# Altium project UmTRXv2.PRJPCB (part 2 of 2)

## Sheet EEpromConfig.SchDoc: BaseBand Front-End
size A3; Revision: 1; SheetNumber: 7
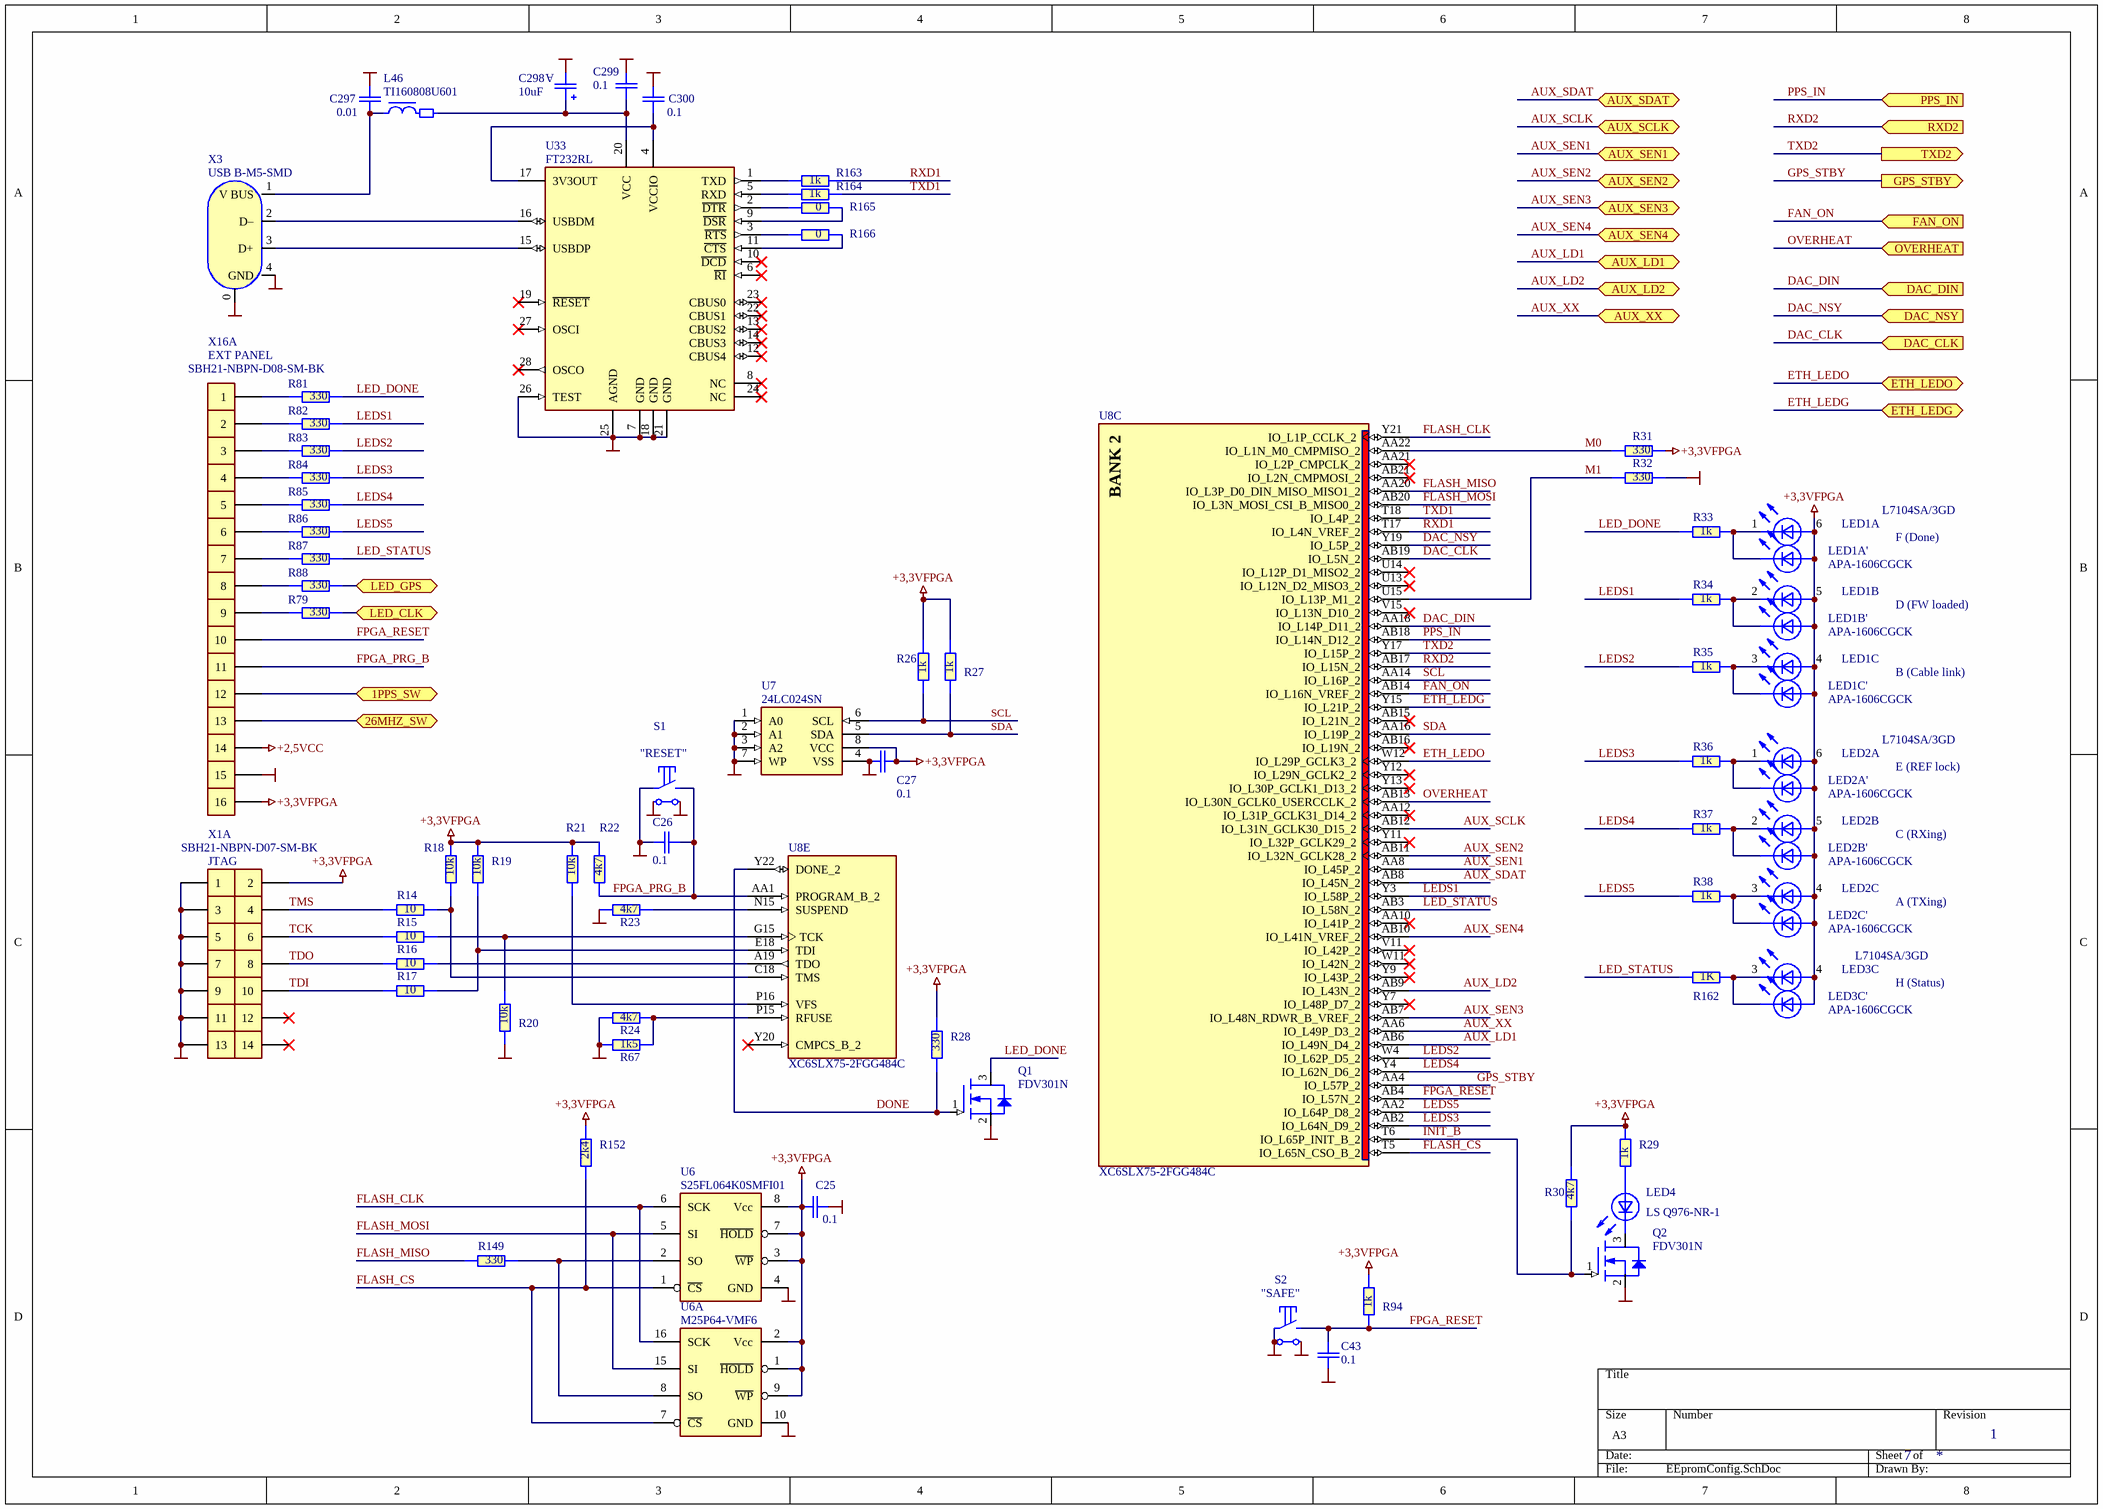
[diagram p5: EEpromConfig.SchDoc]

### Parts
C25  0.1  [C0402-Phillips]
C26  0.1  [C0402-Phillips]
C27  0.1  [C0402-Phillips]
C43  0.1  [C0402-Phillips]
C297  0.01  [C0603-PHILLIPS]
C298  10uF  [CA3216]
C299  0.1  [C0603-PHILLIPS]
C300  0.1  [C0603-PHILLIPS]
L46  TI160808U601  [Ti160808-Phillips]
LED1  L7104SA/3GD  [L-7104SA/3]  (value not drawn)  (parts A,B,C of 3)
LED1A'  APA-1606CGCK  [KPA-1606g]
LED1B'  APA-1606CGCK  [KPA-1606g]
LED1C'  APA-1606CGCK  [KPA-1606g]
LED2  L7104SA/3GD  [L-7104SA/3]  (value not drawn)  (parts A,B,C of 3)
LED2A'  APA-1606CGCK  [KPA-1606g]
LED2B'  APA-1606CGCK  [KPA-1606g]
LED2C'  APA-1606CGCK  [KPA-1606g]
LED3  L7104SA/3GD  [L-7104SA/3]  (part C of 3)
LED3C'  APA-1606CGCK  [KPA-1606g]
LED4  LS Q976-NR-1  [LED-0603y]
Q1  FDV301N  [SOT23-Philips]
Q2  FDV301N  [SOT23-Philips]
R14  10  [R0603-PHILLIPS]
R15  10  [R0603-PHILLIPS]
R16  10  [R0603-PHILLIPS]
R17  10  [R0603-PHILLIPS]
R18  10k  [R0603-PHILLIPS]
R19  10k  [R0603-PHILLIPS]
R20  10k  [R0603-PHILLIPS]
R21  10k  [R0603-PHILLIPS]
R22  4k7  [R0603-PHILLIPS]
R23  4k7  [R0603-PHILLIPS]
R24  4k7  [R0603-PHILLIPS]
R26  1k  [R0603-PHILLIPS]
R27  1k  [R0603-PHILLIPS]
R28  330  [R0603-PHILLIPS]
R29  1k  [R0603-PHILLIPS]
R30  4k7  [R0603-PHILLIPS]
R31  330  [R0603-PHILLIPS]
R32  330  [R0603-PHILLIPS]
R33  1k  [R0603-PHILLIPS]
R34  1k  [R0603-PHILLIPS]
R35  1k  [R0603-PHILLIPS]
R36  1k  [R0603-PHILLIPS]
R37  1k  [R0603-PHILLIPS]
R38  1k  [R0603-PHILLIPS]
R67  1k5  [R0603-PHILLIPS]
R79  330  [R0603-PHILLIPS]
R81  330  [R0603-PHILLIPS]
R82  330  [R0603-PHILLIPS]
R83  330  [R0603-PHILLIPS]
R84  330  [R0603-PHILLIPS]
R85  330  [R0603-PHILLIPS]
R86  330  [R0603-PHILLIPS]
R87  330  [R0603-PHILLIPS]
R88  330  [R0603-PHILLIPS]
R94  1k  [R0603-PHILLIPS]
R149  330  [R0603-PHILLIPS]
R152  2k4  [R0603-PHILLIPS]
R162  1K  [R0603-PHILLIPS]
R163  1k  [R0603-PHILLIPS]
R164  1k  [R0603-PHILLIPS]
R165  0  [R0603-PHILLIPS]
R166  0  [R0603-PHILLIPS]
S1  Misc: "RESET"  [TL3340]  (hidden comment: TL3340AF160QG)
S2  Misc: "SAFE"  [TL3340]  (hidden comment: TL3340AF160QG)
U6  S25FL064K0SMFI01  [SO-8[wide200]]
U6A  M25P64-VMF6  [so-16W]
U7  24LC024SN  [SOIC8]
U8  XC6SLX75-2FGG484C  [FBGA484]  (parts C,E of 8)
U33  FT232RL  [SSOP-28(5.3X10/0.65)]
X1  SBH21-NBPN-D07-SM-BK  Other: JTAG  [SBH-14]  (parts A,B,C,D,E,F,G,H,I,J,K,L,M,N of 14)
X3  USB B-M5-SMD  [USB/SM0.8-6H5]
X16  SBH21-NBPN-D08-SM-BK  Misc: EXT PANEL  [SBH-16]  (parts A,B,C,D,E,F,G,H,I,J,K,L,M,N,O,P of 16)

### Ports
1PPS_SW, 26MHZ_SW, AUX_LD1, AUX_LD2, AUX_SCLK, AUX_SDAT, AUX_SEN1, AUX_SEN2, AUX_SEN3, AUX_SEN4, AUX_XX, DAC_CLK (in), DAC_DIN (in), DAC_NSY (in), ETH_LEDG, ETH_LEDO, FAN_ON (in), GPS_STBY (out), LED_CLK, LED_GPS, OVERHEAT (in), PPS_IN (in), RXD2 (in), TXD2 (out)

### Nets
+2,5VCC: X16.14
+3,3VFPGA: C25.1 C27.2 LED1.4(A3) LED1.5(A2) LED1.6(A1) LED1A'.2(A) LED1B'.2(A) LED1C'.2(A) LED2.4(A3) LED2.5(A2) LED2.6(A1) LED2A'.2(A) LED2B'.2(A) LED2C'.2(A) LED3.4(A3) LED3C'.2(A) R18.1 R19.1 R21.1 R22.1 R26.1 R27.1 R28.1 R29.1 R30.1 R31.2 R94.1 R152.1 U6.3(~{WP}) U6.7(~{HOLD}) U6.8(Vcc) U6A.1(~{HOLD}) U6A.2(Vcc) U6A.9(~{WP}) U7.8(VCC) X1.2 X16.16
GND: C25.2 C26.2 C27.1 C43.1 C297.1 C298.2(-) C299.1 C300.1 Q1.2(S) Q2.2(S) R20.2 R23.1 R24.1 R32.2 R67.1 S1.2 S1.3 S1.4 S2.2 S2.3 S2.4 U6.4(GND) U6A.10(GND) U7.1(A0) U7.2(A1) U7.3(A2) U7.4(VSS) U7.7(WP) U33.7(GND) U33.18(GND) U33.21(GND) U33.25(AGND) U33.26(TEST) X1.1 X1.3 X1.5 X1.7 X1.9 X1.11 X1.13 X3.0(GND) X3.4(GND) X16.15
1PPS_SW: X16.12 ; port 1PPS_SW
26MHZ_SW: X16.13 ; port 26MHZ_SW
AUX_LD1: U8.AB6(IO_L49N_D4_2) ; port AUX_LD1
AUX_LD2: U8.AB9(IO_L43N_2) ; port AUX_LD2
AUX_SCLK: U8.AB12(IO_L31N_GCLK30_D15_2) ; port AUX_SCLK
AUX_SDAT: U8.AB8(IO_L45N_2) ; port AUX_SDAT
AUX_SEN1: U8.AA8(IO_L45P_2) ; port AUX_SEN1
AUX_SEN2: U8.AB11(IO_L32N_GCLK28_2) ; port AUX_SEN2
AUX_SEN3: U8.AB7(IO_L48N_RDWR_B_VREF_2) ; port AUX_SEN3
AUX_SEN4: U8.AB10(IO_L41N_VREF_2) ; port AUX_SEN4
AUX_XX: U8.AA6(IO_L49P_D3_2) ; port AUX_XX
DAC_CLK: U8.AB19(IO_L5N_2) ; port DAC_CLK
DAC_DIN: U8.AA18(IO_L14P_D11_2) ; port DAC_DIN
DAC_NSY: U8.Y19(IO_L5P_2) ; port DAC_NSY
DONE: Q1.1(G) R28.2 U8.Y22(DONE_2)
ETH_LEDG: U8.Y15(IO_L21P_2) ; port ETH_LEDG
ETH_LEDO: U8.W12(IO_L29P_GCLK3_2) ; port ETH_LEDO
FAN_ON: U8.AB14(IO_L16N_VREF_2) ; port FAN_ON
FLASH_CLK: U6.6(SCK) U6A.16(SCK) U8.Y21(IO_L1P_CCLK_2)
FLASH_CS: R152.2 U6.1(~{CS}) U6A.7(~{CS}) U8.T5(IO_L65N_CSO_B_2)
FLASH_MISO: R149.1 U8.AA20(IO_L3P_D0_DIN_MISO_MISO1_2)
FLASH_MOSI: U6.5(SI) U6A.15(SI) U8.AB20(IO_L3N_MOSI_CSI_B_MISO0_2)
FPGA_PRG_B: C26.1 R22.2 S1.1 U8.AA1(PROGRAM_B_2) X16.11
FPGA_RESET: C43.2 R94.2 S2.1 U8.AB4(IO_L57N_2) X16.10
GPS_STBY: U8.AA4(IO_L57P_2) ; port GPS_STBY
INIT_B: Q2.1(G) R30.2 U8.T6(IO_L65P_INIT_B_2)
LED_CLK: R79.2 ; port LED_CLK
LED_DONE: Q1.3(D) R33.2 R81.2
LED_GPS: R88.2 ; port LED_GPS
LED_STATUS: R87.2 R162.1 U8.AB3(IO_L58N_2)
LEDS1: R34.2 R82.2 U8.Y3(IO_L58P_2)
LEDS2: R35.2 R83.2 U8.W4(IO_L62P_D5_2)
LEDS3: R36.2 R84.2 U8.AB2(IO_L64N_D9_2)
LEDS4: R37.2 R85.2 U8.Y4(IO_L62N_D6_2)
LEDS5: R38.2 R86.2 U8.AA2(IO_L64P_D8_2)
M0: R31.1 U8.AA22(IO_L1N_M0_CMPMISO_2)
M1: R32.1 U8.U15(IO_L13P_M1_2)
OVERHEAT: U8.AB13(IO_L30N_GCLK0_USERCCLK_2) ; port OVERHEAT
PPS_IN: U8.AB18(IO_L14N_D12_2) ; port PPS_IN
RXD1: R163.1 U8.T17(IO_L4N_VREF_2)
RXD2: U8.AB17(IO_L15N_2) ; port RXD2
SCL: R26.2 U7.6(SCL) U8.AA14(IO_L16P_2)
SDA: R27.2 U7.5(SDA) U8.AA16(IO_L19P_2)
TCK: R15.1 X1.6
TDI: R17.1 X1.10
TDO: R16.1 X1.8
TMS: R14.1 X1.4
TXD1: R164.1 U8.T18(IO_L4P_2)
TXD2: U8.Y17(IO_L15P_2) ; port TXD2
NetC297_2: C297.2 L46.1 X3.1(V_BUS)
NetC298_1: C298.1(+) C299.2 L46.2 U33.20(VCC)
NetC300_2: C300.2 U33.4(VCCIO) U33.17(3V3OUT)
NetLED1_1: LED1.1(K1) LED1A'.1(K) R33.1
NetLED1_2: LED1.2(K2) LED1B'.1(K) R34.1
NetLED1_3: LED1.3(K3) LED1C'.1(K) R35.1
NetLED2_1: LED2.1(K1) LED2A'.1(K) R36.1
NetLED2_2: LED2.2(K2) LED2B'.1(K) R37.1
NetLED2_3: LED2.3(K3) LED2C'.1(K) R38.1
NetLED3_3: LED3.3(K3) LED3C'.1(K) R162.2
NetLED4_1: LED4.1(K) Q2.3(D)
NetLED4_2: LED4.2(A) R29.2
NetR14_2: R14.2 R18.2 U8.C18(TMS)
NetR15_2: R15.2 R20.1 U8.G15(TCK)
NetR16_2: R16.2 U8.A19(TDO)
NetR17_2: R17.2 R19.2 U8.E18(TDI)
NetR21_2: R21.2 U8.P16(VFS)
NetR23_2: R23.2 U8.N15(SUSPEND)
NetR24_2: R24.2 R67.2 U8.P15(RFUSE)
NetR79_1: R79.1 X16.9
NetR81_1: R81.1 X16.1
NetR82_1: R82.1 X16.2
NetR83_1: R83.1 X16.3
NetR84_1: R84.1 X16.4
NetR85_1: R85.1 X16.5
NetR86_1: R86.1 X16.6
NetR87_1: R87.1 X16.7
NetR88_1: R88.1 X16.8
NetR149_2: R149.2 U6.2(SO) U6A.8(SO)
NetR163_2: R163.2 U33.1(TXD)
NetR164_2: R164.2 U33.5(RXD)
NetR165_1: R165.1 U33.2(~{DTR})
NetR165_2: R165.2 U33.9(~{DSR})
NetR166_1: R166.1 U33.3(~{RTS})
NetR166_2: R166.2 U33.11(~{CTS})
NetU33_15: U33.15(USBDP) X3.3(D+)
NetU33_16: U33.16(USBDM) X3.2(D–)

Not connected (* = marked no-connect by the designer): U8 AA10(IO_L41P_2)* AA12(IO_L31P_GCLK31_D14_2)* AA21(IO_L2P_CMPCLK_2)* AB15(IO_L21N_2)* AB16(IO_L19N_2)* AB21(IO_L2N_CMPMOSI_2)* U13(IO_L12N_D2_MISO3_2)* U14(IO_L12P_D1_MISO2_2)* V11(IO_L42P_2)* V15(IO_L13N_D10_2)* W11(IO_L42N_2)* Y7(IO_L48P_D7_2)* Y9(IO_L43P_2)* Y11(IO_L32P_GCLK29_2)* Y12(IO_L29N_GCLK2_2)* Y13(IO_L30P_GCLK1_D13_2)* Y20(CMPCS_B_2)*; U33 6(~{RI})* 8(NC)* 10(~{DCD})* 12(CBUS4)* 13(CBUS2)* 14(CBUS3)* 19(~{RESET})* 22(CBUS1)* 23(CBUS0)* 24(NC)* 27(OSCI)* 28(OSCO)*; X1 12* 14*

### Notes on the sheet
- F (Done)
- D (FW loaded)
- B (Cable link)
- E (REF lock)
- C (RXing)
- A (TXing)
- H (Status)

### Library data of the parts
C25-C27 C43 = C0402: Конденсатор; Manufacturer: MURATA; Tolerance: 20%; Name: SMD0402; U/P/TKE: Y5V
C297 = C0603: Конденсатор; Manufacturer: MURATA; Tolerance: 20%; Name: SMD0603; U/P/TKE: X7R
C298 = CA3216: Конденсатор; Manufacturer: SPRAGUE; Name: Case A; U/P/TKE: 10V
C299 C300 = C0603: Конденсатор; Manufacturer: MURATA; Tolerance: 20%; Name: SMD0603; U/P/TKE: Y5V
L46 = TI160808: Дроссель ЭМС; Manufacturer: MURATA
LED1-LED3 = L7104SA/3: Светодиод; Manufacturer: KINGBRIGTH; PDF: d:\Proj\Components\Kingbright\L-7104SA-3GD(Ver.4).pdf
LED1A' LED1B' LED1C' LED2A' LED2B' LED2C' LED3C' = KPA-1606: Светодиод; Manufacturer: Kingbright
LED4 = LED0603: LED SMD; Manufacturer: OSRAM Opto Semiconductors Inc
Q1 Q2 = FDV301N: Транзистор; Manufacturer: Fairchild; PDF: D:\Proj\Components\FairChild\FDV301N.pdf
R14-R24 R26-R38 R67 R79 R81-R88 R94 R149 R152 R162-R166 = R0603: Резистор; Manufacturer: YAGEO; Tolerance: 5%; Name: SMD0603; U/P/TKE: 0.1W
S1 S2 = TL3340AF160QG: Switch Tactile SMD right angle; Manufacturer: E-Switch
U6 = S25FL064K: Микросхема; Manufacturer: SPANSION; Swap: No
U6A = M25P64-VMF6: Микросхема; Manufacturer: ST; Swap: No
U7 = AT24CXX: Микросхема; Manufacturer: Microchip; Swap: No; PDF: d:\Proj\components\Atmel\AT24C02A_04A_08A_16A.pdf; PDF2: d:\Proj\Components\Atmel\AT24C04B_08B.pdf
U8 = XC6SLX75-2FGG484C: Spartan-6 LX 1.2V FPGA, 270 User I/Os, 484-Ball Fine-Pitch BGA (1.0mm Pitch), Speed Grade 2, Commercial Grade, Pb-Free; Manufacturer: Xilinx
U33 = FT232RL: Микросхема; Manufacturer: FTDI; Misc: USB UART Asynchronous Serial Data Transfer Chip,
X1 = SBH21-7x2_SMD: Разъем; Manufacturer: Sullins
X3 = USB M-1J: Разъём
X16 = SBH21-8x2_SMD: Connector 2mm SMD; Manufacturer: Sullins

## Sheet Clocking.SchDoc: BaseBand Front-End
size A3; Revision: 1; SheetNumber: 5
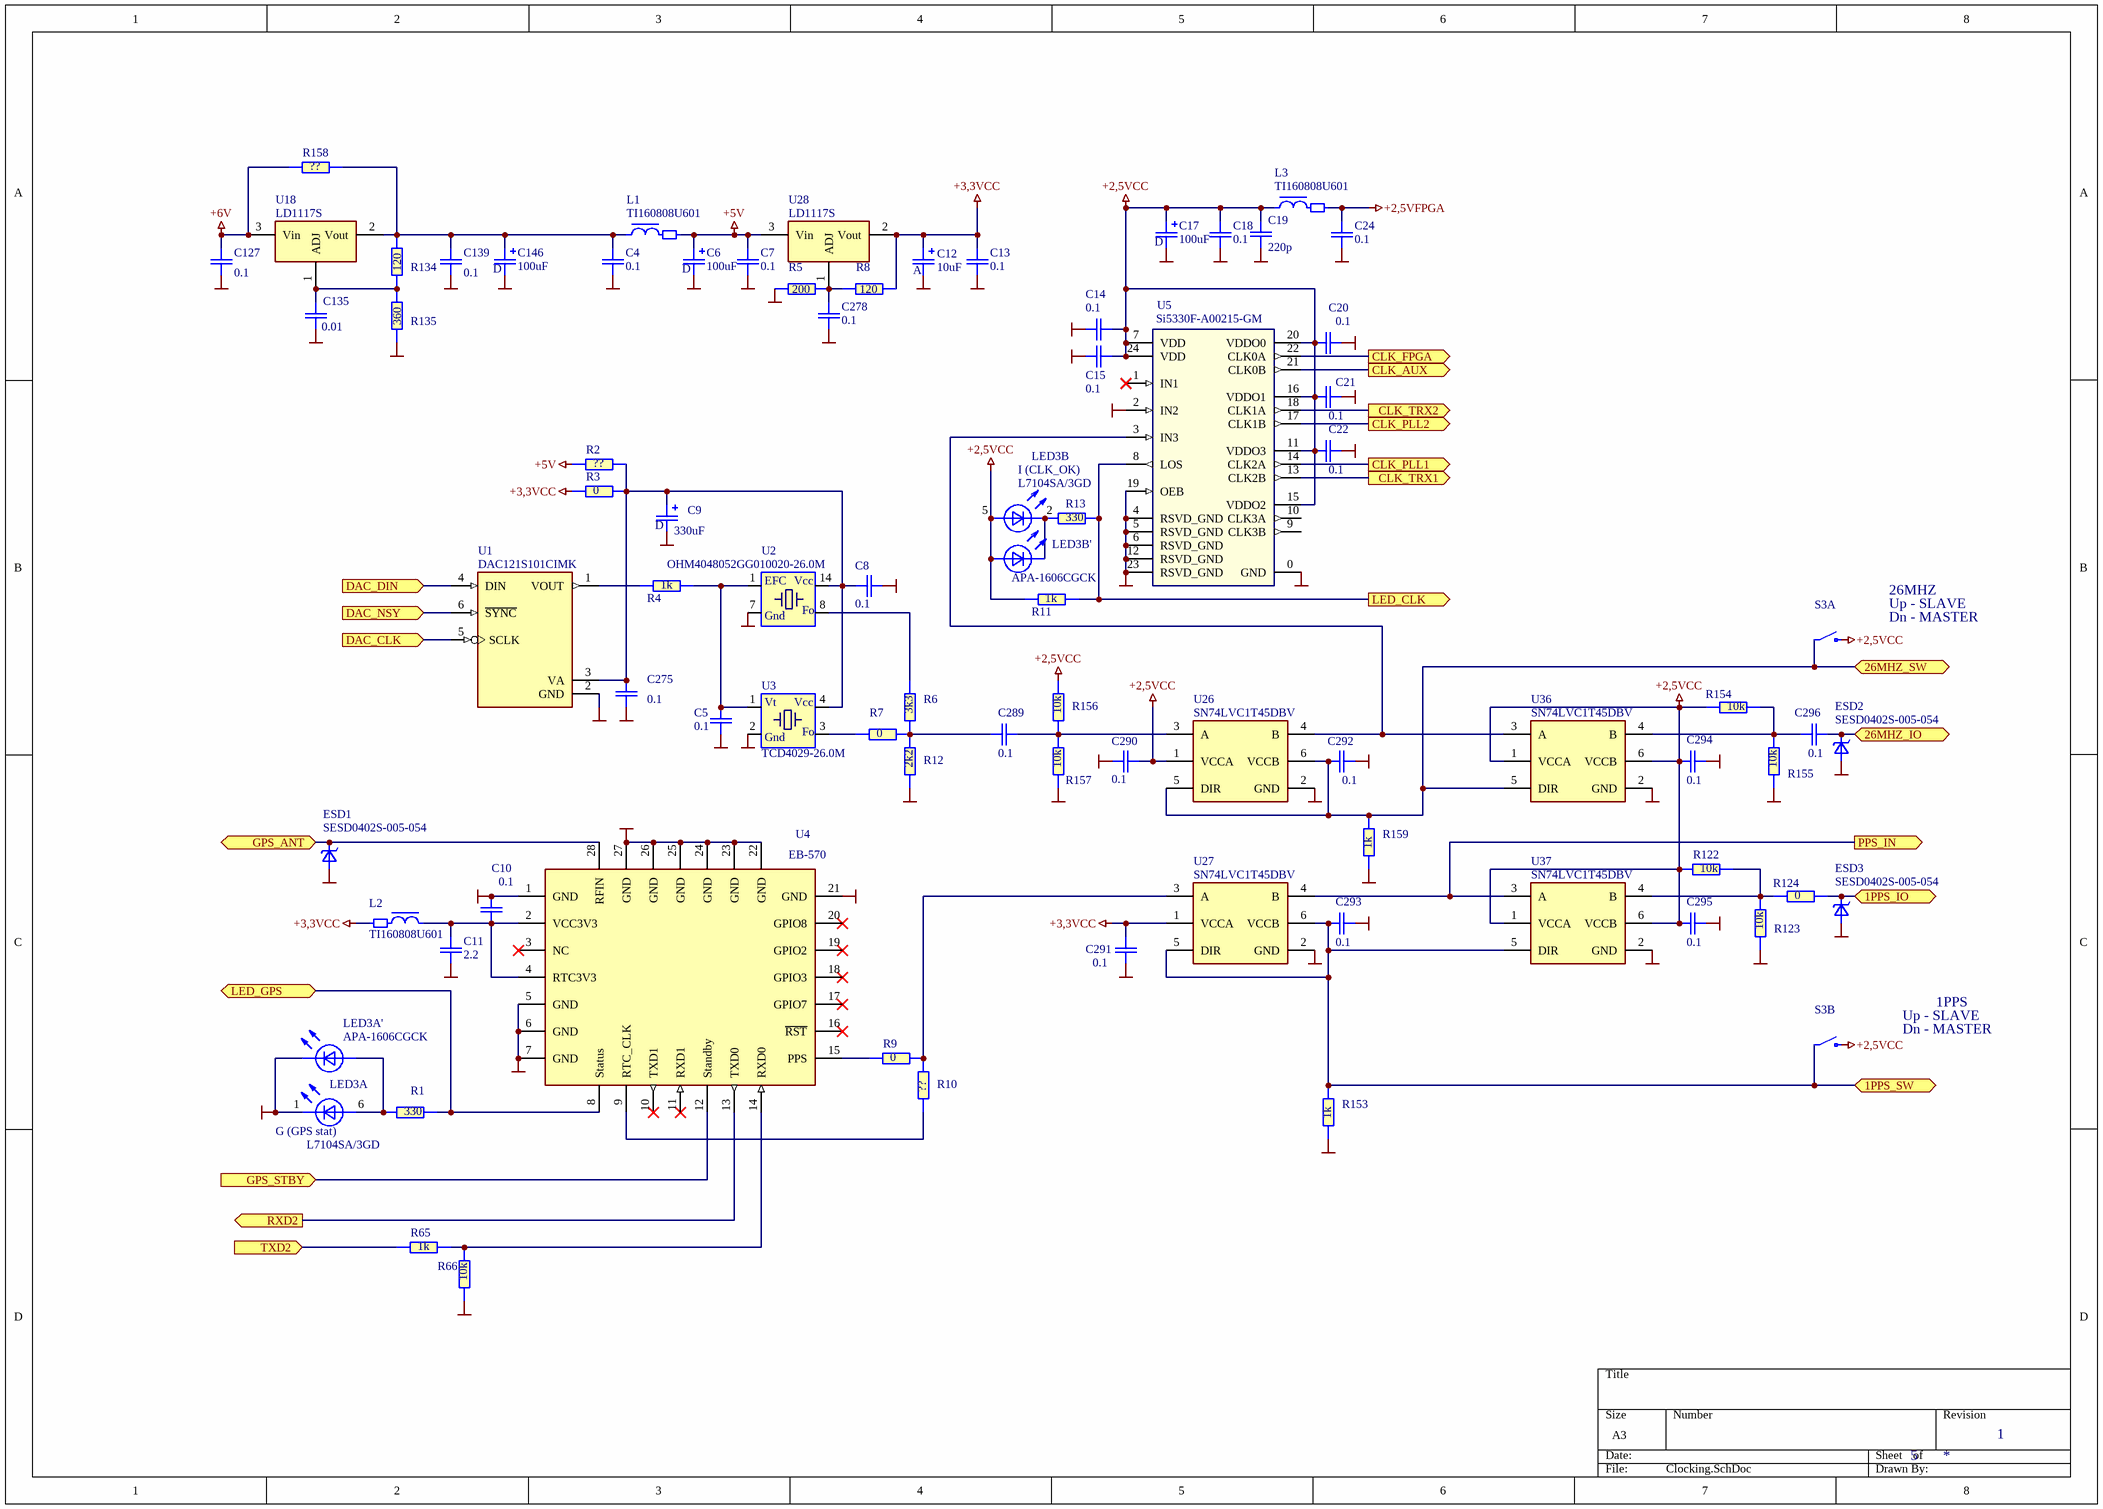
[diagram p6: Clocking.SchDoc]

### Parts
C4  0.1  [C0402-Phillips]
C5  0.1  [C0402-Phillips]
C6  100uF  [cd7343]
C7  0.1  [C0402-Phillips]
C8  0.1  [C0402-Phillips]
C9  330uF  [cd7343]
C10  0.1  [C0402-Phillips]
C11  2.2  [C0402-Phillips]
C12  10uF  [CA3216]
C13  0.1  [C0402-Phillips]
C14  0.1  [C0402-Phillips]
C15  0.1  [C0402-Phillips]
C17  100uF  [cd7343]
C18  0.1  [C0402-Phillips]
C19  220p  [C0603-PHILLIPS]
C20  0.1  [C0402-Phillips]
C21  0.1  [C0402-Phillips]
C22  0.1  [C0402-Phillips]
C24  0.1  [C0402-Phillips]
C127  0.1  [C0402-Phillips]
C135  0.01  [C0402-Phillips]
C139  0.1  [C0402-Phillips]
C146  100uF  [cd7343]
C275  0.1  [C0402-Phillips]
C278  0.1  [C0402-Phillips]
C289  0.1  [C0402-Phillips]
C290  0.1  [C0402-Phillips]
C291  0.1  [C0402-Phillips]
C292  0.1  [C0402-Phillips]
C293  0.1  [C0402-Phillips]
C294  0.1  [C0402-Phillips]
C295  0.1  [C0402-Phillips]
C296  0.1  [C0402-Phillips]
ESD1  SESD0402S-005-054  [SESD0402-Phillips]
ESD2  SESD0402S-005-054  [SESD0402-Phillips]
ESD3  SESD0402S-005-054  [SESD0402-Phillips]
L1  TI160808U601  [Ti160808-Phillips]
L2  TI160808U601  [Ti160808-Phillips]
L3  TI160808U601  [Ti160808-Phillips]
LED3  L7104SA/3GD  [L-7104SA/3]  (parts A,B of 3)
LED3A'  APA-1606CGCK  [KPA-1606g]
LED3B'  APA-1606CGCK  [KPA-1606g]
R1  330  [R0603-PHILLIPS]
R2  ??  [R0603-PHILLIPS]
R3  0  [R0603-PHILLIPS]
R4  1k  [R0603-PHILLIPS]
R5  200  [R0603-PHILLIPS]
R6  3k3  [R0603-PHILLIPS]
R7  0  [R0603-PHILLIPS]
R8  120  [R0603-PHILLIPS]
R9  0  [R0603-PHILLIPS]
R10  ??  [R0603-PHILLIPS]
R11  1k  [R0603-PHILLIPS]
R12  2k2  [R0603-PHILLIPS]
R13  330  [R0603-PHILLIPS]
R65  1k  [R0603-PHILLIPS]
R66  10k  [R0603-PHILLIPS]
R122  10k  [R0603-PHILLIPS]
R123  10k  [R0603-PHILLIPS]
R124  0  [R0603-PHILLIPS]
R134  120  [R0603-PHILLIPS]
R135  360  [R0603-PHILLIPS]
R153  1k  [R0603-PHILLIPS]
R154  10k  [R0603-PHILLIPS]
R155  10k  [R0603-PHILLIPS]
R156  10k  [R0603-PHILLIPS]
R157  10k  [R0603-PHILLIPS]
R158  ??  [R0603-PHILLIPS]
R159  1k  [R0603-PHILLIPS]
S3  CHP-021A  [CHP-02xA]  (value not drawn)  (parts A,B of 2)
U1  DAC121S101CIMK  [SOT-23-6]
U2  OHM4048052GG010020-26.0M  [DIL14-20x13,2]
U3  TCD4029-26.0M  [TCXO5X3]
U4  EB-570  [EB-570]
U5  Si5330F-A00215-GM  [QFN-24(4x4/0/5mm) with Pad]
U18  LD1117S  [SOT-223-1]
U26  SN74LVC1T45DBV  [SOT-23-6-min]
U27  SN74LVC1T45DBV  [SOT-23-6-min]
U28  LD1117S  [SOT-223-1]
U36  SN74LVC1T45DBV  [SOT-23-6-min]
U37  SN74LVC1T45DBV  [SOT-23-6-min]

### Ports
1PPS_IO, 1PPS_SW, 26MHZ_IO, 26MHZ_SW, CLK_AUX (out), CLK_FPGA (out), CLK_PLL1 (out), CLK_PLL2 (out), CLK_TRX1 (out), CLK_TRX2 (out), DAC_CLK (in), DAC_DIN (in), DAC_NSY (in), GPS_ANT, GPS_STBY (in), LED_CLK (out), LED_GPS, PPS_IN (out), RXD2 (out), TXD2 (in)

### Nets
+2,5VCC: C14.2 C15.2 C17.1(+) C18.1 C19.1 C20.1 C21.1 C22.1 C290.1 C294.2 C295.2 L3.1 LED3.5(A2) LED3B'.2(A) R11.1 R122.2 R154.2 R156.1 S3.3 S3.4 U5.7(VDD) U5.11(VDDO3) U5.15(VDDO2) U5.16(VDDO1) U5.20(VDDO0) U5.24(VDD) U26.1(VCCA) U36.1(VCCA) U36.6(VCCB) U37.1(VCCA) U37.6(VCCB)
+2,5VFPGA: C24.1 L3.2
+3,3VCC: C12.1(+) C13.1 C291.1 L2.2 R3.1 R8.2 U27.1(VCCA) U28.2(Vout)
+5V: C6.1(+) C7.1 L1.2 R2.1 U28.3(Vin)
+6V: C127.1 R158.1 U18.3(Vin)
GND: C4.2 C5.1 C6.2(-) C7.2 C8.2 C9.2(-) C10.2 C11.2 C12.2(-) C13.2 C14.1 C15.1 C17.2(-) C18.2 C19.2 C20.2 C21.2 C22.2 C24.2 C127.2 C135.2 C139.2 C146.2(-) C275.1 C278.2 C290.2 C291.2 C292.1 C293.1 C294.1 C295.1 ESD1.2(A) ESD2.2(A) ESD3.2(A) LED3.1(K1) LED3A'.1(K) R5.1 R12.1 R66.1 R123.2 R135.2 R153.1 R155.2 R157.2 R159.1 U1.2(GND) U2.7(GND) U3.2(GND) U4.1(GND) U4.5(GND) U4.6(GND) U4.7(GND) U4.21(GND) U4.22(GND) U4.23(GND) U4.24(GND) U4.25(GND) U4.26(GND) U4.27(GND) U5.0(GND) U5.2(IN2) U5.4(RSVD_GND) U5.5(RSVD_GND) U5.6(RSVD_GND) U5.12(RSVD_GND) U5.19(OEB) U5.23(RSVD_GND) U26.2(GND) U27.2(GND) U36.2(GND) U37.2(GND)
1PPS_IO: ESD3.1(K) R124.1 ; port 1PPS_IO
1PPS_SW: C293.2 R153.2 S3.2 U27.5(DIR) U27.6(VCCB) U37.5(DIR) ; port 1PPS_SW
26MHZ_IO: C296.1 ESD2.1(K) ; port 26MHZ_IO
26MHZ_SW: C292.2 R159.2 S3.1 U26.5(DIR) U26.6(VCCB) U36.5(DIR) ; port 26MHZ_SW
CLK_AUX: U5.21(CLK0B) ; port CLK_AUX
CLK_FPGA: U5.22(CLK0A) ; port CLK_FPGA
CLK_PLL1: U5.14(CLK2A) ; port CLK_PLL1
CLK_PLL2: U5.17(CLK1B) ; port CLK_PLL2
CLK_TRX1: U5.13(CLK2B) ; port CLK_TRX1
CLK_TRX2: U5.18(CLK1A) ; port CLK_TRX2
DAC_CLK: U1.5(SCLK) ; port DAC_CLK
DAC_DIN: U1.4(DIN) ; port DAC_DIN
DAC_NSY: U1.6(~{SYNC}) ; port DAC_NSY
GPS_ANT: ESD1.1(K) U4.28(RFIN) ; port GPS_ANT
GPS_STBY: U4.12(Standby) ; port GPS_STBY
LED_CLK: R11.2 R13.2 U5.8(LOS) ; port LED_CLK
LED_GPS: R1.2 U4.8(Status) ; port LED_GPS
PPS_IN: U27.4(B) U37.3(A) ; port PPS_IN
RXD2: U4.13(TXD0) ; port RXD2
TXD2: R65.1 ; port TXD2
NetC4_1: C4.1 C139.1 C146.1(+) L1.1 R134.1 R158.2 U18.2(Vout)
NetC5_2: C5.2 R4.2 U2.1(EFC) U3.1(Vtune)
NetC8_1: C8.1 C9.1(+) C275.2 R2.2 R3.2 U1.3(VA) U2.14(VCC) U3.4(VCC)
NetC10_1: C10.1 C11.1 L2.1 U4.2(VCC3V3) U4.4(RTC3V3)
NetC135_1: C135.1 R134.2 R135.1 U18.1(ADJ)
NetC278_1: C278.1 R5.2 R8.1 U28.1(ADJ)
NetC289_1: C289.1 R156.2 R157.1 U26.3(A)
NetC289_2: C289.2 R6.2 R7.2 R12.2
NetC296_2: C296.2 R154.1 R155.1 U36.4(B)
NetLED3_2: LED3.2(K2) LED3B'.1(K) R13.1
NetLED3_6: LED3.6(A1) LED3A'.2(A) R1.1
NetR4_1: R4.1 U1.1(VOUT)
NetR6_1: R6.1 U2.8(Fo)
NetR7_1: R7.1 U3.3(Fo)
NetR9_1: R9.1 U4.15(PPS)
NetR9_2: R9.2 R10.2 U27.3(A)
NetR10_1: R10.1 U4.9(RTC_CLK)
NetR65_2: R65.2 R66.2 U4.14(RXD0)
NetR122_1: R122.1 R123.1 R124.2 U37.4(B)
NetU5_3: U5.3(IN3) U26.4(B) U36.3(A)

Not connected (* = marked no-connect by the designer): U4 3(NC)* 10(TXD1)* 11(RXD1)* 16(~{RST})* 17(GPIO7)* 18(GPIO3)* 19(GPIO2)* 20(GPIO8)*; U5 1(IN1)* 9(CLK3B) 10(CLK3A)

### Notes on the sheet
- I (CLK_OK)
- (near S3) Dn - MASTER
- Up - SLAVE
- 26MHZ
- Dn - MASTER
- 1PPS
- (near LED3) G (GPS stat)

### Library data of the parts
C4 C5 C7 C8 C10 C11 C13-C15 C18 C20-C22 C24 C127 C135 C139 C275 C278 C289-C296 = C0402: as C25-C27 on sheet EEpromConfig
C6 C17 C146 = CD7343: Конденсатор; Manufacturer: SPRAGUE; Name: CASE-G; U/P/TKE: 16V
C9 = CD7343: Конденсатор; Manufacturer: Kemet; Name: CASE-D; U/P/TKE: 10V
C12 = CA3216: as C298 on sheet EEpromConfig
C19 = C0603: Конденсатор; Manufacturer: MURATA; Tolerance: 20%; Name: SMD0603; U/P/TKE: NP0
ESD1-ESD3 = SESD0402S: ESD diod unidirectional; Manufacturer: Tyco Electronics Corp; U/P/TKE: 5.4V
L1-L3 = TI160808: Дроссель ЭМС; Manufacturer: MURATA
LED3 = L7104SA/3: as LED1 on sheet EEpromConfig
LED3A' LED3B' = KPA-1606: Светодиод; Manufacturer: Kingbright
R1-R13 R65 R66 R122-R124 R134 R135 R153-R159 = R0603: as R14-R24 on sheet EEpromConfig
S3 = CHP-021A: Switch 2pos Piano SMD right angle; Manufacturer: Copal Electronics
U1 = DAC121S101CIMK: Микросхема; Manufacturer: National Semiconductor; Misc: 12-Bit Micro Power Digital-to-Analog Converter with Rail-to-Rail Output
U2 = OCVCXO: Manufacturer: Pletronics; Misc: TCXO
U3 = TCVCXO_5X3: TCVCXO; Manufacturer: Pletronics; Misc: TCXO
U4 = EB-570: Микросхема; Manufacturer: Transystem Inc.; Misc: GPS receiver module
U5 = SI5330: Микросхема; Manufacturer: Silicon Laboratoryes; Misc: CLOCK BUFFER/LEVEL TRANSLATOR; Swap: No
U18 U28 = LD1117ADJ: Микросхема; Manufacturer: STMicro; Swap: No
U26 U27 U36 U37 = SN74LVC1T45DBV: Микросхема; Manufacturer: TI; Swap: No; Misc: Single-bit noninverting bus transceiver; PDF: d:\Proj\Components\Texas Instruments\SN74LVC1T45DBV.pdf

## Sheet LMS.SchDoc
size A3; Revision: 1; SheetNumber: 3
Used 2 times, as channels LMS-a, LMS-b. Parts and nets are listed once, with the designators drawn on the sheet.
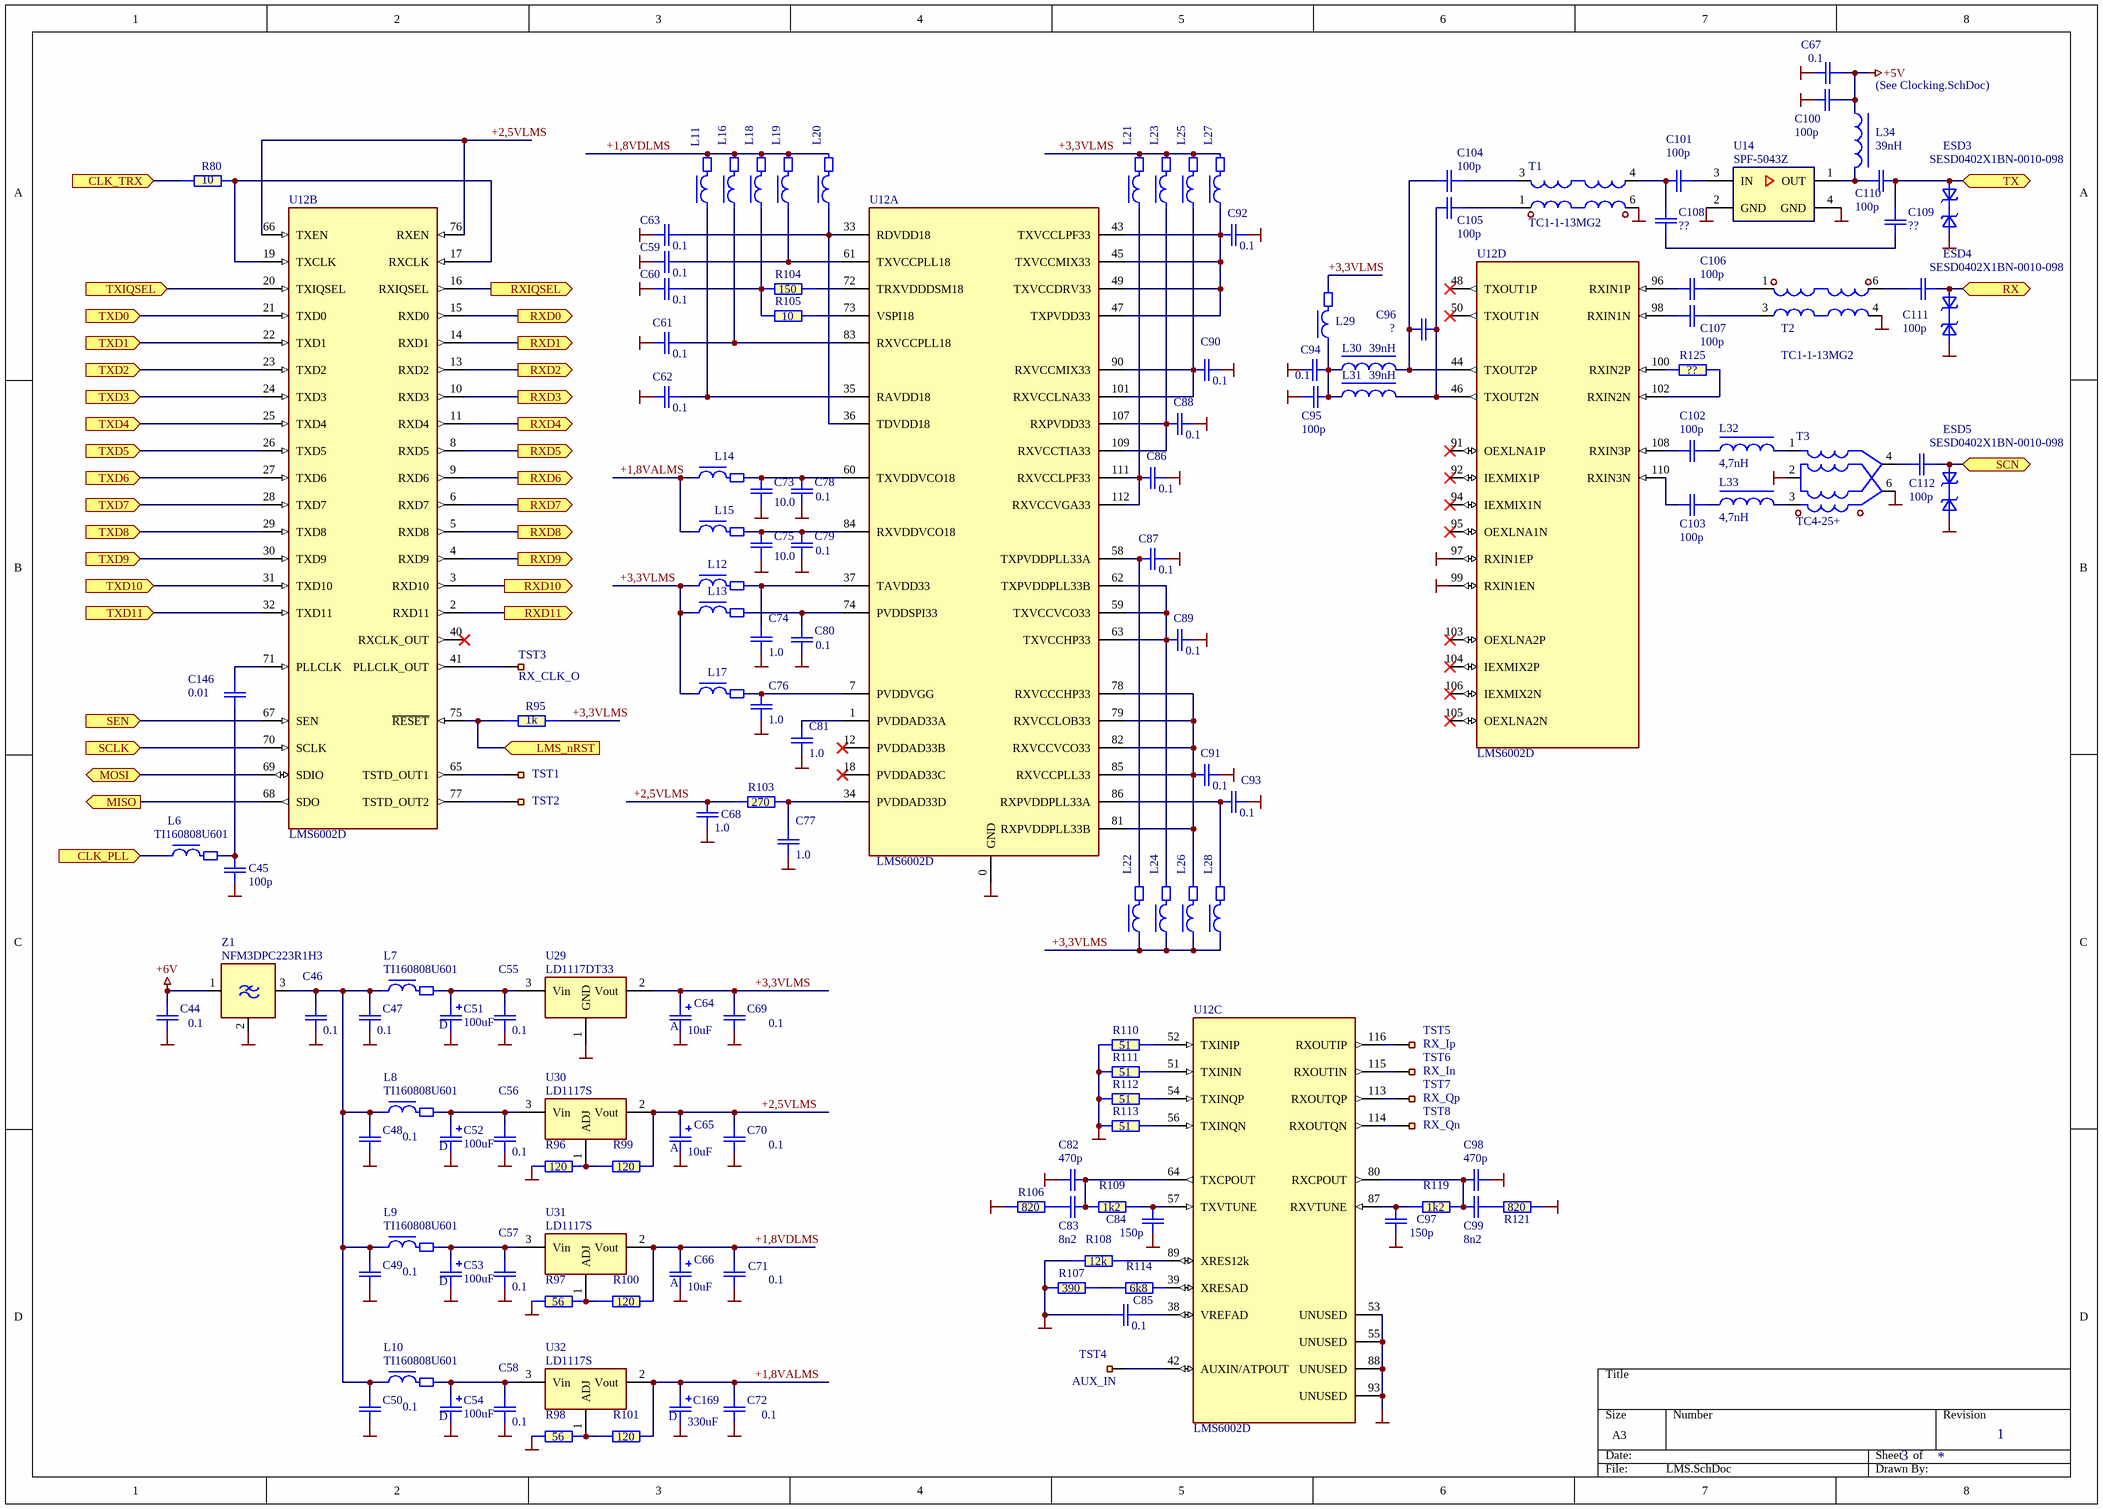
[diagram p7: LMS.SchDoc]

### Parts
C44  0.1  [C0402-Phillips]
C45  100p  [C0603-PHILLIPS]
C46  0.1  [C0402-Phillips]
C47  0.1  [C0402-Phillips]
C48  0.1  [C0402-Phillips]
C49  0.1  [C0402-Phillips]
C50  0.1  [C0402-Phillips]
C51  100uF  [cd7343]
C52  100uF  [cd7343]
C53  100uF  [cd7343]
C54  100uF  [cd7343]
C55  0.1  [C0402-Phillips]
C56  0.1  [C0402-Phillips]
C57  0.1  [C0402-Phillips]
C58  0.1  [C0402-Phillips]
C59  0.1  [C0402-Phillips]
C60  0.1  [C0402-Phillips]
C61  0.1  [C0402-Phillips]
C62  0.1  [C0402-Phillips]
C63  0.1  [C0402-Phillips]
C64  10uF  [CA3216]
C65  10uF  [CA3216]
C66  10uF  [CA3216]
C67  0.1  [C0402-Phillips]
C68  1.0  [C0603-PHILLIPS]
C69  0.1  [C0402-Phillips]
C70  0.1  [C0402-Phillips]
C71  0.1  [C0402-Phillips]
C72  0.1  [C0402-Phillips]
C73  10.0  [C0603-Phillips]
C74  1.0  [C0603-PHILLIPS]
C75  10.0  [C0603-Phillips]
C76  1.0  [C0603-PHILLIPS]
C77  1.0  [C0603-PHILLIPS]
C78  0.1  [C0402-Phillips]
C79  0.1  [C0402-cirq]
C80  0.1  [C0402-cirq]
C81  1.0  [C0603-PHILLIPS]
C82  470p  [C0603-PHILLIPS]
C83  8n2  [C0603-PHILLIPS]
C84  150p  [C0603-PHILLIPS]
C85  0.1  [C0402-Phillips]
C86  0.1  [C0402-Phillips]
C87  0.1  [C0402-Phillips]
C88  0.1  [C0402-cirq]
C89  0.1  [C0402-cirq]
C90  0.1  [C0402-Phillips]
C91  0.1  [C0402-Phillips]
C92  0.1  [C0402-cirq]
C93  0.1  [C0402-Phillips]
C94  0.1  [C0402-Phillips]
C95  100p  [C0603-PHILLIPS]
C96  ?  [C0603-PHILLIPS]
C97  150p  [C0603-PHILLIPS]
C98  470p  [C0603-PHILLIPS]
C99  8n2  [C0603-PHILLIPS]
C100  100p  [C0603-PHILLIPS]
C101  100p  [C0603-PHILLIPS]
C102  100p  [C0603-PHILLIPS]
C103  100p  [C0603-PHILLIPS]
C104  100p  [C0603-PHILLIPS]
C105  100p  [C0603-PHILLIPS]
C106  100p  [C0603-PHILLIPS]
C107  100p  [C0603-PHILLIPS]
C108  ??  [C0603-PHILLIPS]
C109  ??  [C0603-PHILLIPS]
C110  100p  [C0603-PHILLIPS]
C111  100p  [C0603-PHILLIPS]
C112  100p  [C0603-PHILLIPS]
C146  0.01  [C0603-PHILLIPS]
C169  330uF  [cd7343]
ESD3  SESD0402X1BN-0010-098  [R0402-Phillips]
ESD4  SESD0402X1BN-0010-098  [R0402-Phillips]
ESD5  SESD0402X1BN-0010-098  [R0402-Phillips]
L6  TI160808U601  [Ti160808-Phillips]
L7  TI160808U601  [Ti160808-Phillips]
L8  TI160808U601  [Ti160808-Phillips]
L9  TI160808U601  [Ti160808-Phillips]
L10  TI160808U601  [Ti160808-Phillips]
L11  TI160808U601  [Ti160808-Phillips]  (value not drawn)
L12  TI160808U601  [Ti160808-Phillips]  (value not drawn)
L13  TI160808U601  [Ti160808-Phillips]  (value not drawn)
L14  TI160808U601  [Ti160808-Phillips]  (value not drawn)
L15  TI160808U601  [Ti160808-Phillips]  (value not drawn)
L16  TI160808U601  [Ti160808-Phillips]  (value not drawn)
L17  TI160808U601  [Ti160808-Phillips]  (value not drawn)
L18  TI160808U601  [Ti160808-Phillips]  (value not drawn)
L19  TI160808U601  [Ti160808-Phillips]  (value not drawn)
L20  TI160808U601  [Ti160808-Phillips]  (value not drawn)
L21  TI160808U601  [Ti160808-Phillips]  (value not drawn)
L22  TI160808U601  [Ti160808-Phillips]  (value not drawn)
L23  TI160808U601  [Ti160808-Phillips]  (value not drawn)
L24  TI160808U601  [Ti160808-Phillips]  (value not drawn)
L25  TI160808U601  [Ti160808-Phillips]  (value not drawn)
L26  TI160808U601  [Ti160808-Phillips]  (value not drawn)
L27  TI160808U601  [Ti160808-Phillips]  (value not drawn)
L28  TI160808U601  [Ti160808-Phillips]  (value not drawn)
L29  TI160808U601  [Ti160808-Phillips]  (value not drawn)
L30  39nH  [TF160808-Phillips]
L31  39nH  [TF160808-Phillips]
L32  4,7nH  [TF160808-Phillips]
L33  4,7nH  [TF160808-Phillips]
L34  39nH  [TF160808-Phillips]
R80  10  [R0603-PHILLIPS]
R95  1k  [R0603-PHILLIPS]
R96  120  [R0603-PHILLIPS]
R97  56  [R0603-PHILLIPS]
R98  56  [R0603-PHILLIPS]
R99  120  [R0603-PHILLIPS]
R100  120  [R0603-PHILLIPS]
R101  120  [R0603-PHILLIPS]
R103  270  [R0603-PHILLIPS]
R104  150  [R0603-PHILLIPS]
R105  10  [R0603-PHILLIPS]
R106  820  [R0603-PHILLIPS]
R107  390  [R0603-PHILLIPS]
R108  12k  [R0603-PHILLIPS]
R109  1k2  [R0603-PHILLIPS]
R110  51  [R0603-PHILLIPS]
R111  51  [R0603-PHILLIPS]
R112  51  [R0603-PHILLIPS]
R113  51  [R0603-PHILLIPS]
R114  6k8  [R0603-PHILLIPS]
R119  1k2  [R0603-PHILLIPS]
R121  820  [R0603-PHILLIPS]
R125  ??  [R0603-PHILLIPS]
T1  TC1-1-13MG2  [AT224-1]
T2  TC1-1-13MG2  [AT224-1]
T3  TC4-25+  [AT224-1]
TST1  (no value)  [kp40x40]
TST2  (no value)  [kp40x40]
TST3  RX_CLK_O  [kp40x40]
TST4  AUX_IN  [kp40x40]
TST5  RX_Ip  [kp40x40]
TST6  RX_In  [kp40x40]
TST7  RX_Qp  [kp40x40]
TST8  RX_Qn  [kp40x40]
U12  LMS6002D  [DQFN120(9x9/0.5mm)]  (parts A,B,C,D of 4)
U14  SPF-5043Z  [SOT-343[2X1.25]]
U29  LD1117DT33  [to-252]
U30  LD1117S  [SOT-223-1]
U31  LD1117S  [SOT-223-1]
U32  LD1117S  [SOT-223-1]
Z1  NFM3DPC223R1H3  [NFM3DP]

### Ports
CLK_PLL (in), CLK_TRX (in), LMS_nRST (in), MISO (out), MOSI (bidir), RX, RXD0 (out), RXD1 (out), RXD2 (out), RXD3 (out), RXD4 (out), RXD5 (out), RXD6 (out), RXD7 (out), RXD8 (out), RXD9 (out), RXD10 (out), RXD11 (out), RXIQSEL (out), SCLK (in), SCN, SEN (in), TX, TXD0 (in), TXD1 (in), TXD2 (in), TXD3 (in), TXD4 (in), TXD5 (in), TXD6 (in), TXD7 (in), TXD8 (in), TXD9 (in), TXD10 (in), TXD11 (in), TXIQSEL (in)

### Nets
+5V: C67.2 C100.2 L34.1
+6V: C44.1 Z1.1
GND: C44.2 C45.1 C46.2 C47.2 C48.2 C49.2 C50.2 C51.2(-) C52.2(-) C53.2(-) C54.2(-) C55.2 C56.2 C57.2 C58.2 C59.1 C60.1 C61.1 C62.1 C63.1 C64.2(-) C65.2(-) C66.2(-) C67.1 C68.2 C69.2 C70.2 C71.2 C72.2 C73.2 C74.2 C75.2 C76.2 C77.2 C78.2 C79.2 C80.2 C81.2 C82.2 C84.1 C85.1 C86.2 C87.2 C88.2 C89.2 C90.2 C91.2 C92.2 C93.2 C94.1 C95.2 C97.1 C98.2 C100.1 C169.2(-) ESD3.1(A1) ESD4.1(A1) ESD5.1(A1) R96.1 R97.1 R98.1 R106.1 R107.1 R108.1 R110.1 R111.1 R112.1 R113.1 R121.2 T1.6(Pri_Dot) T2.4(Pri) T3.2(Sec_CT) T3.6(Pri_Dot) U12.0(GND) U12.53(UNUSED) U12.55(UNUSED) U12.88(UNUSED) U12.93(UNUSED) U12.97(RXIN1EP) U12.99(RXIN1EN) U14.2(GND) U14.4(GND) U29.1(GND) Z1.2
+1,8VALMS: C72.1 C169.1(+) L14.1 L15.1 R101.2 U32.2(Vout)
+1,8VDLMS: C66.1(+) C71.1 L11.2 L16.2 L18.2 L19.2 L20.2 R100.2 U31.2(Vout)
+2,5VLMS: C65.1(+) C68.1 C70.1 R99.2 R103.1 U12.66(TXEN) U12.76(RXEN) U30.2(Vout)
+3,3VLMS: C64.1(+) C69.1 L12.1 L13.1 L17.1 L21.2 L22.1 L23.2 L24.1 L25.2 L26.1 L27.2 L28.1 L29.2 R95.2 U29.2(Vout)
CLK_PLL: L6.1 ; port CLK_PLL
CLK_TRX: R80.1 ; port CLK_TRX
LMS_nRST: R95.1 U12.75(~{RESET}) ; port LMS_nRST
MISO: U12.68(SDO) ; port MISO
MOSI: U12.69(SDIO) ; port MOSI
RX: C111.1 ESD4.2(A2) ; port RX
RXD0: U12.15(RXD0) ; port RXD0
RXD1: U12.14(RXD1) ; port RXD1
RXD2: U12.13(RXD2) ; port RXD2
RXD3: U12.10(RXD3) ; port RXD3
RXD4: U12.11(RXD4) ; port RXD4
RXD5: U12.8(RXD5) ; port RXD5
RXD6: U12.9(RXD6) ; port RXD6
RXD7: U12.6(RXD7) ; port RXD7
RXD8: U12.5(RXD8) ; port RXD8
RXD9: U12.4(RXD9) ; port RXD9
RXD10: U12.3(RXD10) ; port RXD10
RXD11: U12.2(RXD11) ; port RXD11
RXIQSEL: U12.16(RXIQSEL) ; port RXIQSEL
SCLK: U12.70(SCLK) ; port SCLK
SCN: C112.2 ESD5.2(A2) ; port SCN
SEN: U12.67(SEN) ; port SEN
TX: C109.2 C110.2 ESD3.2(A2) ; port TX
TXD0: U12.21(TXD0) ; port TXD0
TXD1: U12.22(TXD1) ; port TXD1
TXD2: U12.23(TXD2) ; port TXD2
TXD3: U12.24(TXD3) ; port TXD3
TXD4: U12.25(TXD4) ; port TXD4
TXD5: U12.26(TXD5) ; port TXD5
TXD6: U12.27(TXD6) ; port TXD6
TXD7: U12.28(TXD7) ; port TXD7
TXD8: U12.29(TXD8) ; port TXD8
TXD9: U12.30(TXD9) ; port TXD9
TXD10: U12.31(TXD10) ; port TXD10
TXD11: U12.32(TXD11) ; port TXD11
TXIQSEL: U12.20(TXIQSEL) ; port TXIQSEL
NetC45_2: C45.2 C146.1 L6.2
NetC46_1: C46.1 C47.1 C48.1 C49.1 C50.1 L7.1 L8.1 L9.1 L10.1 Z1.3
NetC51_1: C51.1(+) C55.1 L7.2 U29.3(Vin)
NetC52_1: C52.1(+) C56.1 L8.2 U30.3(Vin)
NetC53_1: C53.1(+) C57.1 L9.2 U31.3(Vin)
NetC54_1: C54.1(+) C58.1 L10.2 U32.3(Vin)
NetC59_2: C59.2 L19.1 U12.61(TXVCCPLL18)
NetC60_2: C60.2 L18.1 R104.1 R105.1
NetC61_2: C61.2 L16.1 U12.83(RXVCCPLL18)
NetC62_2: C62.2 L11.1 U12.35(RAVDD18)
NetC63_2: C63.2 L20.1 U12.33(RDVDD18) U12.36(TDVDD18)
NetC73_1: C73.1 C78.1 L14.2 U12.60(TXVDDVCO18)
NetC74_1: C74.1 L12.2 U12.37(TAVDD33)
NetC75_1: C75.1 C79.1 L15.2 U12.84(RXVDDVCO18)
NetC76_1: C76.1 L17.2 U12.7(PVDDVGG)
NetC77_1: C77.1 R103.2 U12.34(PVDDAD33D)
NetC80_1: C80.1 L13.2 U12.74(PVDDSPI33)
NetC81_1: C81.1 U12.1(PVDDAD33A)
NetC82_1: C82.1 C83.1 R109.1 U12.64(TXCPOUT)
NetC83_2: C83.2 R106.2
NetC84_2: C84.2 R109.2 U12.57(TXVTUNE)
NetC85_2: C85.2 U12.38(VREFAD)
NetC86_1: C86.1 L21.1 U12.111(RXVCCLPF33) U12.112(RXVCCVGA33)
NetC87_1: C87.1 L22.2 U12.58(TXPVDDPLL33A)
NetC88_1: C88.1 L23.1 U12.107(RXPVDD33) U12.109(RXVCCTIA33)
NetC89_1: C89.1 L24.2 U12.59(TXVCCVCO33) U12.62(TXPVDDPLL33B) U12.63(TXVCCHP33)
NetC90_1: C90.1 L25.1 U12.90(RXVCCMIX33) U12.101(RXVCCLNA33)
NetC91_1: C91.1 L26.2 U12.78(RXVCCCHP33) U12.79(RXVCCLOB33) U12.81(RXPVDDPLL33B) U12.82(RXVCCVCO33) U12.85(RXVCCPLL33)
NetC92_1: C92.1 L27.1 U12.43(TXVCCLPF33) U12.45(TXVCCMIX33) U12.47(TXPVDD33) U12.49(TXVCCDRV33)
NetC93_1: C93.1 L28.2 U12.86(RXPVDDPLL33A)
NetC94_2: C94.2 C95.1 L29.1 L30.1 L31.1
NetC96_1: C96.1 C105.1 L31.2 U12.46(TXOUT2N)
NetC96_2: C96.2 C104.1 L30.2 U12.44(TXOUT2P)
NetC97_2: C97.2 R119.1 U12.87(RXVTUNE)
NetC98_1: C98.1 C99.1 R119.2 U12.80(RXCPOUT)
NetC99_2: C99.2 R121.1
NetC101_1: C101.1 C108.1 T1.4(Pri)
NetC101_2: C101.2 U14.3(IN)
NetC102_1: C102.1 U12.108(RXIN3P)
NetC102_2: C102.2 L32.1
NetC103_1: C103.1 U12.110(RXIN3N)
NetC103_2: C103.2 L33.1
NetC104_2: C104.2 T1.3(Sec_Dot)
NetC105_2: C105.2 T1.1(Sec)
NetC106_1: C106.1 U12.96(RXIN1P)
NetC106_2: C106.2 T2.1(Sec)
NetC107_1: C107.1 U12.98(RXIN1N)
NetC107_2: C107.2 T2.3(Sec_Dot)
NetC108_2: C108.2 C109.1
NetC110_1: C110.1 L34.2 U14.1(OUT)
NetC111_2: C111.2 T2.6(Pri_Dot)
NetC112_1: C112.1 T3.4(Pri)
NetC146_2: C146.2 U12.71(PLLCLK)
NetL32_2: L32.2 T3.1(Sec)
NetL33_2: L33.2 T3.3(Sec_Dot)
NetR80_2: R80.2 U12.17(RXCLK) U12.19(TXCLK)
NetR96_2: R96.2 R99.1 U30.1(ADJ)
NetR97_2: R97.2 R100.1 U31.1(ADJ)
NetR98_2: R98.2 R101.1 U32.1(ADJ)
NetR104_2: R104.2 U12.72(TRXVDDDSM18)
NetR105_2: R105.2 U12.73(VSPI18)
NetR107_2: R107.2 R114.1
NetR108_2: R108.2 U12.89(XRES12k)
NetR110_2: R110.2 U12.52(TXINIP)
NetR111_2: R111.2 U12.51(TXININ)
NetR112_2: R112.2 U12.54(TXINQP)
NetR113_2: R113.2 U12.56(TXINQN)
NetR114_2: R114.2 U12.39(XRESAD)
NetR125_1: R125.1 U12.100(RXIN2P)
NetR125_2: R125.2 U12.102(RXIN2N)
NetTST1_1: TST1.1 U12.65(TSTD_OUT1)
NetTST2_1: TST2.1 U12.77(TSTD_OUT2)
NetTST3_1: TST3.1 U12.41(PLLCLK_OUT)
NetTST4_1: TST4.1 U12.42(AUXIN/ATPOUT)
NetTST5_1: TST5.1 U12.116(RXOUTIP)
NetTST6_1: TST6.1 U12.115(RXOUTIN)
NetTST7_1: TST7.1 U12.113(RXOUTQP)
NetTST8_1: TST8.1 U12.114(RXOUTQN)

Not connected (* = marked no-connect by the designer): U12 12(PVDDAD33B)* 18(PVDDAD33C)* 40(RXCLK_OUT)* 48(TXOUT1P)* 50(TXOUT1N)* 91(OEXLNA1P)* 92(IEXMIX1P)* 94(IEXMIX1N)* 95(OEXLNA1N)* 103(OEXLNA2P)* 104(IEXMIX2P)* 105(OEXLNA2N)* 106(IEXMIX2N)*

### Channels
LMS-a: designators end in -1; ports CLK_PLL=CLK_PLL1 CLK_TRX=CLK_TRX1 LMS_nRST=LMS1_nRST MISO=MISO1 MOSI=MOSI1 RX=RX RXD0=RX1D0 RXD1=RX1D1 RXD2=RX1D2 RXD3=RX1D3 RXD4=RX1D4 RXD5=RX1D5 RXD6=RX1D6 RXD7=RX1D7 RXD8=RX1D8 RXD9=RX1D9 RXD10=RX1D10 RXD11=RX1D11 RXIQSEL=RX1IQSEL SCLK=SCLK1 SCN=SCN SEN=SEN1 TX=TX TXD0=TX1D0 TXD1=TX1D1 TXD2=TX1D2 TXD3=TX1D3 TXD4=TX1D4 TXD5=TX1D5 TXD6=TX1D6 TXD7=TX1D7 TXD8=TX1D8 TXD9=TX1D9 TXD10=TX1D10 TXD11=TX1D11 TXIQSEL=TX1IQSEL
LMS-b: designators end in -2; ports CLK_PLL=CLK_PLL2 CLK_TRX=CLK_TRX2 LMS_nRST=LMS2_nRST MISO=MISO2 MOSI=MOSI2 RX=RX RXD0=RX2D0 RXD1=RX2D1 RXD2=RX2D2 RXD3=RX2D3 RXD4=RX2D4 RXD5=RX2D5 RXD6=RX2D6 RXD7=RX2D7 RXD8=RX2D8 RXD9=RX2D9 RXD10=RX2D10 RXD11=RX2D11 RXIQSEL=RX2IQSEL SCLK=SCLK2 SCN=SCN SEN=SEN2 TX=TX TXD0=TX2D0 TXD1=TX2D1 TXD2=TX2D2 TXD3=TX2D3 TXD4=TX2D4 TXD5=TX2D5 TXD6=TX2D6 TXD7=TX2D7 TXD8=TX2D8 TXD9=TX2D9 TXD10=TX2D10 TXD11=TX2D11 TXIQSEL=TX2IQSEL

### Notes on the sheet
- (See Clocking.SchDoc)

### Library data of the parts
C44 C46-C50 C55-C63 C67 C69-C72 C78-C80 C85-C94 = C0402: as C25-C27 on sheet EEpromConfig
C45 C82-C84 C95-C112 C146 = C0603: as C19 on sheet Clocking
C51-C54 = CD7343: as C6 on sheet Clocking
C64-C66 = CA3216: Конденсатор; Manufacturer: SPRAGUE; Name: Case A; U/P/TKE: 16V
C68 C73-C77 C81 = C0603: as C299 on sheet EEpromConfig
C169 = CD7343: as C9 on sheet Clocking
ESD3-ESD5 = SESD0402X: ESD diod bi-directional; Manufacturer: Tyco Electronics Corp; U/P/TKE: 9.8V
L6-L29 = TI160808: Дроссель ЭМС; Manufacturer: MURATA
L30-L34 = TF160808: Индуктивность; Manufacturer: SMD
R80 R95-R101 R103-R114 R119 R121 R125 = R0603: as R14-R24 on sheet EEpromConfig
T1 T2 = TC1-1-13: Трансформатор; Manufacturer: Mini-Cirquits; PDF: d:\Proj\Components\Mini-Circuits\TC1-1-13MG2+.pdf; Misc: RF Transformer
T3 = TC4-25: Трансформатор; Manufacturer: Mini-Cirquits; PDF: d:\Proj\Components\Mini-Circuits\TC4-25+.pdf; Misc: RF Transformer
TST1-TST8 = KP: Контактная площадка; Manufacturer: Конструктив
U12 = LMS6002D: Микросхема; Manufacturer: Lime Microsystems; Misc: Multi-band Multi-standard  Transceiver with Digital Interface
U14 = SPF-5043Z: Микросхема; Manufacturer: RFMD; Swap: No; PDF: D:\Proj\Components\Sirenza\SPF-5043Z_Datasheet.pdf
U29 = LD1117FIX: Микросхема; Manufacturer: STMicro; Swap: No
U30-U32 = LD1117ADJ: as U18 on sheet Clocking
Z1 = NFM3DP: Фильтр; Manufacturer: Murata; Misc: Фильтр электромагнитных помех; Value: 0.022uF; PDF: D:\DataSheets\MuRata\EMI_FILTERS.pdf

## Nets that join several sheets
+2,5VCC: EEpromConfig (X16.14), Clocking (31 pins)
+2,5VETH: PwrAndBias (22 pins), GBEthernet (12 pins)
+2,5VFPGA: PwrAndBias (65 pins), Clocking (C24.1 L3.2)
+2,5VRAM: PwrAndBias (20 pins), FPGA_RAM (U11.97)
+3,3VFPGA: PwrAndBias (61 pins), GBEthernet (C42.1 L5.2), EEpromConfig (37 pins)
+5V: Clocking (5 pins), LMS-a (C67-1.2 C100-1.2 L34-1.1), LMS-b (C67-2.2 C100-2.2 L34-2.1)
+6V: Total (X12.16), PwrAndBias (C125.1 L44.2), Clocking (C127.1 R158.1 U18.3), LMS-a (C44-1.1 Z1-1.1), LMS-b (C44-2.1 Z1-2.1)
GND: Total (12 pins), PwrAndBias (245 pins), FPGA_RAM (6 pins), GBEthernet (19 pins), EEpromConfig (43 pins), Clocking (71 pins), LMS-a (84 pins), LMS-b (84 pins)
1PPS_IO: Total (X13.1 X13'.1), Clocking (ESD3.1 R124.1)
1PPS_SW: EEpromConfig (X16.12), Clocking (6 pins)
26MHZ_IO: Total (X7.1), Clocking (C296.1 ESD2.1)
26MHZ_SW: EEpromConfig (X16.13), Clocking (6 pins)
AUX_LD1: Total (X12.11), EEpromConfig (U8.AB6)
AUX_LD2: Total (X12.12), EEpromConfig (U8.AB9)
AUX_SCLK: Total (X12.6), EEpromConfig (U8.AB12)
AUX_SDAT: Total (X12.5), EEpromConfig (U8.AB8)
AUX_SEN1: Total (X12.7), EEpromConfig (U8.AA8)
AUX_SEN2: Total (X12.8), EEpromConfig (U8.AB11)
AUX_SEN3: Total (X12.9), EEpromConfig (U8.AB7)
AUX_SEN4: Total (X12.10), EEpromConfig (U8.AB10)
AUX_XX: Total (X12.13), EEpromConfig (U8.AA6)
CLK_AUX: Total (X12.14), Clocking (U5.21)
CLK_FPGA: FPGA_RAM (U8.M3), Clocking (U5.22)
CLK_PLL1: Clocking (U5.14), LMS-a (L6-1.1)
CLK_PLL2: Clocking (U5.17), LMS-b (L6-2.1)
CLK_TO_MAC: FPGA_RAM (U8.K20), GBEthernet (R89.2)
CLK_TRX1: Clocking (U5.13), LMS-a (R80-1.1)
CLK_TRX2: Clocking (U5.18), LMS-b (R80-2.1)
DAC_CLK: EEpromConfig (U8.AB19), Clocking (U1.5)
DAC_DIN: EEpromConfig (U8.AA18), Clocking (U1.4)
DAC_NSY: EEpromConfig (U8.Y19), Clocking (U1.6)
DivSw1_N: Total (X12.2), FPGA_RAM (U8.M1)
DivSw1_P: Total (X12.1), FPGA_RAM (U8.M2)
DivSw2_N: Total (X12.4), FPGA_RAM (U8.K1)
DivSw2_P: Total (X12.3), FPGA_RAM (U8.K2)
ETH_LEDG: GBEthernet (R44.2), EEpromConfig (U8.Y15)
ETH_LEDO: GBEthernet (R42.2), EEpromConfig (U8.W12)
FAN_ON: PwrAndBias (U35.4), EEpromConfig (U8.AB14)
GMII_COL: FPGA_RAM (U8.N22), GBEthernet (RA2.11)
GMII_CRS: FPGA_RAM (U8.P20), GBEthernet (RA2.12)
GMII_GTX_CLK: FPGA_RAM (U8.H21), GBEthernet (RA2.14)
GMII_RX_CLK: FPGA_RAM (U8.H22), GBEthernet (RA2.10)
GMII_RX_DV: FPGA_RAM (U8.L22), GBEthernet (RA3.16)
GMII_RX_ER: FPGA_RAM (U8.M22), GBEthernet (RA2.9)
GMII_RXD0: FPGA_RAM (U8.L20), GBEthernet (RA3.15)
GMII_RXD1: FPGA_RAM (U8.K22), GBEthernet (RA3.14)
GMII_RXD2: FPGA_RAM (U8.K21), GBEthernet (RA3.13)
GMII_RXD3: FPGA_RAM (U8.F18), GBEthernet (RA3.12)
GMII_RXD4: FPGA_RAM (U8.J20), GBEthernet (RA3.11)
GMII_RXD5: FPGA_RAM (U8.F19), GBEthernet (RA3.10)
GMII_RXD6: FPGA_RAM (U8.F20), GBEthernet (RA3.9)
GMII_RXD7: FPGA_RAM (U8.G22), GBEthernet (R90.1)
GMII_TX_CLK: FPGA_RAM (U8.J22), GBEthernet (RA2.13)
GMII_TX_EN: FPGA_RAM (U8.T19), GBEthernet (RA2.16)
GMII_TX_ER: FPGA_RAM (U8.R22), GBEthernet (RA2.15)
GMII_TXD0: FPGA_RAM (U8.T22), GBEthernet (RA1.9)
GMII_TXD1: FPGA_RAM (U8.T21), GBEthernet (RA1.10)
GMII_TXD2: FPGA_RAM (U8.U22), GBEthernet (RA1.11)
GMII_TXD3: FPGA_RAM (U8.U20), GBEthernet (RA1.12)
GMII_TXD4: FPGA_RAM (U8.V22), GBEthernet (RA1.13)
GMII_TXD5: FPGA_RAM (U8.V21), GBEthernet (RA1.14)
GMII_TXD6: FPGA_RAM (U8.W22), GBEthernet (RA1.15)
GMII_TXD7: FPGA_RAM (U8.W20), GBEthernet (RA1.16)
GPS_ANT: Total (R175.2 X6.1), Clocking (ESD1.1 U4.28)
GPS_STBY: EEpromConfig (U8.AA4), Clocking (U4.12)
LED_CLK: EEpromConfig (R79.2), Clocking (R11.2 R13.2 U5.8)
LED_GPS: EEpromConfig (R88.2), Clocking (R1.2 U4.8)
LMS1_nRST: FPGA_RAM (U8.L3), LMS-a (R95-1.1 U12-1.75)
LMS2_nRST: FPGA_RAM (U8.Y1), LMS-b (R95-2.1 U12-2.75)
MDC: FPGA_RAM (U8.F22), GBEthernet (U9.55)
MDIO: FPGA_RAM (U8.F21), GBEthernet (R92.2 U9.54)
MISO1: FPGA_RAM (TST12.1 U8.F2), LMS-a (U12-1.68)
MISO2: FPGA_RAM (TST16.1 U8.N6), LMS-b (U12-2.68)
MOSI1: FPGA_RAM (TST11.1 U8.E3), LMS-a (U12-1.69)
MOSI2: FPGA_RAM (TST15.1 U8.M7), LMS-b (U12-2.69)
OVERHEAT: PwrAndBias (R173.2 U35.6), EEpromConfig (U8.AB13)
PHY_INTN: FPGA_RAM (U8.E22), GBEthernet (R91.2 U9.53)
PHY_RESETn: FPGA_RAM (U8.R20), GBEthernet (U9.24)
PPS_IN: EEpromConfig (U8.AB18), Clocking (U27.4 U37.3)
RX: Total (X9.1), LMS-a (C111-1.1 ESD4-1.2)
RX: Total (X10.1), LMS-b (C111-2.1 ESD4-2.2)
RX1D0: FPGA_RAM (U8.J1), LMS-a (U12-1.15)
RX1D1: FPGA_RAM (U8.L6), LMS-a (U12-1.14)
RX1D2: FPGA_RAM (U8.H3), LMS-a (U12-1.13)
RX1D3: FPGA_RAM (U8.K6), LMS-a (U12-1.10)
RX1D4: FPGA_RAM (U8.K5), LMS-a (U12-1.11)
RX1D5: FPGA_RAM (U8.H2), LMS-a (U12-1.8)
RX1D6: FPGA_RAM (U8.J3), LMS-a (U12-1.9)
RX1D7: FPGA_RAM (U8.K4), LMS-a (U12-1.6)
RX1D8: FPGA_RAM (U8.J6), LMS-a (U12-1.5)
RX1D9: FPGA_RAM (U8.M8), LMS-a (U12-1.4)
RX1D10: FPGA_RAM (U8.J7), LMS-a (U12-1.3)
RX1D11: FPGA_RAM (U8.N7), LMS-a (U12-1.2)
RX1IQSEL: FPGA_RAM (U8.J4), LMS-a (U12-1.16)
RX2D0: FPGA_RAM (U8.T2), LMS-b (U12-2.15)
RX2D1: FPGA_RAM (U8.T3), LMS-b (U12-2.14)
RX2D2: FPGA_RAM (U8.U1), LMS-b (U12-2.13)
RX2D3: FPGA_RAM (U8.T4), LMS-b (U12-2.10)
RX2D4: FPGA_RAM (U8.V3), LMS-b (U12-2.11)
RX2D5: FPGA_RAM (U8.T1), LMS-b (U12-2.8)
RX2D6: FPGA_RAM (U8.U3), LMS-b (U12-2.9)
RX2D7: FPGA_RAM (U8.U4), LMS-b (U12-2.6)
RX2D8: FPGA_RAM (U8.V2), LMS-b (U12-2.5)
RX2D9: FPGA_RAM (U8.V1), LMS-b (U12-2.4)
RX2D10: FPGA_RAM (U8.W1), LMS-b (U12-2.3)
RX2D11: FPGA_RAM (U8.W3), LMS-b (U12-2.2)
RX2IQSEL: FPGA_RAM (U8.P8), LMS-b (U12-2.16)
RXD2: EEpromConfig (U8.AB17), Clocking (U4.13)
SCLK1: FPGA_RAM (TST10.1 U8.F1), LMS-a (U12-1.70)
SCLK2: FPGA_RAM (TST14.1 U8.H5), LMS-b (U12-2.70)
SCN: Total (X14.1), LMS-a (C112-1.2 ESD5-1.2)
SCN: Total (X15.1), LMS-b (C112-2.2 ESD5-2.2)
SEN1: FPGA_RAM (TST9.1 U8.E1), LMS-a (U12-1.67)
SEN2: FPGA_RAM (TST13.1 U8.M4), LMS-b (U12-2.67)
TX: Total (X8.1), LMS-a (C109-1.2 C110-1.2 ESD3-1.2)
TX: Total (X11.1), LMS-b (C109-2.2 C110-2.2 ESD3-2.2)
TX1D0: FPGA_RAM (U8.H4), LMS-a (U12-1.21)
TX1D1: FPGA_RAM (U8.H8), LMS-a (U12-1.22)
TX1D2: FPGA_RAM (U8.G4), LMS-a (U12-1.23)
TX1D3: FPGA_RAM (U8.G7), LMS-a (U12-1.24)
TX1D4: FPGA_RAM (U8.F5), LMS-a (U12-1.25)
TX1D5: FPGA_RAM (U8.F7), LMS-a (U12-1.26)
TX1D6: FPGA_RAM (U8.G6), LMS-a (U12-1.27)
TX1D7: FPGA_RAM (U8.E5), LMS-a (U12-1.28)
TX1D8: FPGA_RAM (U8.F3), LMS-a (U12-1.29)
TX1D9: FPGA_RAM (U8.E4), LMS-a (U12-1.30)
TX1D10: FPGA_RAM (U8.H1), LMS-a (U12-1.31)
TX1D11: FPGA_RAM (U8.E6), LMS-a (U12-1.32)
TX1IQSEL: FPGA_RAM (U8.H6), LMS-a (U12-1.20)
TX2D0: FPGA_RAM (U8.R3), LMS-b (U12-2.21)
TX2D1: FPGA_RAM (U8.L4), LMS-b (U12-2.22)
TX2D2: FPGA_RAM (U8.R1), LMS-b (U12-2.23)
TX2D3: FPGA_RAM (U8.K7), LMS-b (U12-2.24)
TX2D4: FPGA_RAM (U8.P2), LMS-b (U12-2.25)
TX2D5: FPGA_RAM (U8.K8), LMS-b (U12-2.26)
TX2D6: FPGA_RAM (U8.P1), LMS-b (U12-2.27)
TX2D7: FPGA_RAM (U8.P4), LMS-b (U12-2.28)
TX2D8: FPGA_RAM (U8.P5), LMS-b (U12-2.29)
TX2D9: FPGA_RAM (U8.P6), LMS-b (U12-2.30)
TX2D10: FPGA_RAM (U8.P3), LMS-b (U12-2.31)
TX2D11: FPGA_RAM (U8.N3), LMS-b (U12-2.32)
TX2IQSEL: FPGA_RAM (U8.M5), LMS-b (U12-2.20)
TXD2: EEpromConfig (U8.Y17), Clocking (R65.1)

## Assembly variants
UmTRXv2_2U_20dBm_TCXO: not fitted C96-1 C96-2 C108-1 C108-2 C109-1 C109-2 LED1A' LED1B' LED1C' LED2A' LED2B' LED2C' LED3A' LED3B' LED3C' R2 R6 R10 R12 R52 R53 R54 R62 R79 R81 R82 R83 R84 R85 R86 R87 R88 R125-1 R125-2 R158 R172 R175 U2 U6 X2-1 X2-2 X6' X13' X16
UmTRXv2_20dBm_TCXO: not fitted C96-1 C96-2 C108-1 C108-2 C109-1 C109-2 LED1 LED2 LED3 R2 R6 R10 R12 R52 R53 R54 R62 R79 R81 R82 R83 R84 R85 R86 R87 R88 R125-1 R125-2 R158 R172 R175 U2 U6 X2-1 X2-2 X6' X13' X16
UmTRXv2_empty: not fitted C4 C5 C6 C7 C8 C9 C10 C11 C12 C13 C14 C15 C17 C18 C19 C20 C21 C22 C24 C25 C26 C27 C32 C33 C34 C35 C36 C37 C38 C39 C40 C41 C42 C43 C44-1 C44-2 C45-1 C45-2 C46-1 C46-2 C47-1 C47-2 C48-1 C48-2 C49-1 C49-2 C50-1 C50-2 C51-1 C51-2 C52-1 C52-2 C53-1 C53-2 C54-1 C54-2 C55-1 C55-2 C56-1 C56-2 C57-1 C57-2 C58-1 C58-2 C59-1 C59-2 C60-1 C60-2 C61-1 C61-2 C62-1 C62-2 C63-1 C63-2 C64-1 C64-2 C65-1 C65-2 C66-1 C66-2 C67-1 C67-2 C68-1 C68-2 C69-1 C69-2 C70-1 C70-2 C71-1 C71-2 C72-1 C72-2 C73-1 C73-2 C74-1 C74-2 C75-1 C75-2 C76-1 C76-2 C77-1 C77-2 C78-1 C78-2 C79-1 C79-2 C80-1 C80-2 C81-1 C81-2 C82-1 C82-2 C83-1 C83-2 C84-1 C84-2 C85-1 C85-2 C86-1 C86-2 C87-1 C87-2 C88-1 C88-2 C89-1 C89-2 C90-1 C90-2 C91-1 C91-2 C92-1 C92-2 C93-1 C93-2 C94-1 C94-2 C95-1 C95-2 C96-1 C96-2 C97-1 C97-2 C98-1 C98-2 C99-1 C99-2 C100-1 C100-2 C101-1 C101-2 C102-1 C102-2 C103-1 C103-2 C104-1 C104-2 C105-1 C105-2 C106-1 C106-2 C107-1 C107-2 C108-1 C108-2 C109-1 C109-2 C110-1 C110-2 C111-1 C111-2 C112-1 C112-2 C113 C114 C115 C116 C117 C118 C119 C120 C125 C127 C128 C129 C131 C132 C133 C135 C136 C137 C138 C139 C140 C141 C143 C144 C145 C146 C146-1 C146-2 C147 C148 C150 C151 C152 C153 C154 C156 C157 C158 C159 C161 C162 C163 C164 C165 C166 C167 C168 C169-1 C169-2 C171 C172 C174 C175 C176 C177 C178 C179 C180 C181 C182 C183 C184 C185 C186 C187 C188 C189 C190 C191 C192 C193 C194 C196 C197 C198 C199 C200 C201 C202 C203 C204 C205 C206 C207 C208 C209 C210 C211 C212 C213 C214 C215 C216 C217 C218 C219 C220 C221 C222 C223 C224 C225 C227 C228 C229 C230 C231 C232 C233 C234 C235 C236 C237 C238 C239 C240 C241 C242 C243 C244 C245 C246 C247 C248 C249 C250 C251 C252 C254 C255 C256 C257 C258 C259 C260 C261 C262 C263 C264 C265 C266 C267 C268 C269 C270 C271 C272 C273 C274 C275 C276 C277 C278 C279 C280 C281 C282 C283 C284 C285 C286 C287 C289 C290 C291 C292 C293 C294 C295 C296 C297 C298 C299 C300 D1 D2 D3 D4 ESD1 ESD2 ESD3 ESD3-1 ESD3-2 ESD4-1 ESD4-2 ESD5-1 ESD5-2 F1 L1 L2 L3 L4 L5 L6-1 L6-2 L7-1 L7-2 L8-1 L8-2 L9-1 L9-2 L10-1 L10-2 L11-1 L11-2 L12-1 L12-2 L13-1 L13-2 L14-1 L14-2 L15-1 L15-2 L16-1 L16-2 L17-1 L17-2 L18-1 L18-2 L19-1 L19-2 L20-1 L20-2 L21-1 L21-2 L22-1 L22-2 L23-1 L23-2 L24-1 L24-2 L25-1 L25-2 L26-1 L26-2 L27-1 L27-2 L28-1 L28-2 L29-1 L29-2 L30-1 L30-2 L31-1 L31-2 L32-1 L32-2 L33-1 L33-2 L34-1 L34-2 L35 L36 L37 L40 L41 L42 L43 L44 L45 L46 LED1 LED1A' LED1B' LED1C' LED2 LED2A' LED2B' LED2C' LED3 LED3A' LED3B' LED3C' LED4 LED5 LED6 Q1 Q2 Q3 Q4 R1 R2 R3 R4 R5 R6 R7 R8 R9 R10 R11 R12 R13 R14 R15 R16 R17 R18 R19 R20 R21 R22 R23 R24 R26 R27 R28 R29 R30 R31 R32 R33 R34 R35 R36 R37 R38 R41 R42 R43 R44 R45 R46 R47 R48 R49 R50 R51 R52 R53 R54 R55 R56 R57 R58 R59 R60 R61 R62 R63 R64 R65 R66 R67 R78 R79 R80-1 R80-2 R81 R82 R83 R84 R85 R86 R87 R88 R89 R90 R91 R92 R93 R94 R95-1 R95-2 R96-1 R96-2 R97-1 R97-2 R98-1 R98-2 R99-1 R99-2 R100-1 R100-2 R101-1 R101-2 R103-1 R103-2 R104-1 R104-2 R105-1 R105-2 R106-1 R106-2 R107-1 R107-2 R108-1 R108-2 R109-1 R109-2 R110-1 R110-2 R111-1 R111-2 R112-1 R112-2 R113-1 R113-2 R114-1 R114-2 R119-1 R119-2 R121-1 R121-2 R122 R123 R124 R125-1 R125-2 R128 R129 R131 R132 R133 R134 R135 R136 R137 R138 R149 R152 R153 R154 R155 R156 R157 R158 R159 R162 R163 R164 R165 R166 R168 R169 R170 R171 R172 R173 R174 R175 RA1 RA2 RA3 S1 S2 S3 T1-1 T1-2 T2-1 T2-2 T3-1 T3-2 TST1-1 TST1-2 TST2-1 TST2-2 TST3-1 TST3-2 TST4-1 TST4-2 TST5-1 TST5-2 TST6-1 TST6-2 TST7-1 TST7-2 TST8-1 TST8-2 TST9 TST10 TST11 TST12 TST13 TST14 TST15 TST16 U1 U2 U3 U4 U5 U6 U6A U7 U8 U9 U10 U11 U12-1 U12-2 U14-1 U14-2 U15 U16 U17 U18 U26 U27 U28 U29-1 U29-2 U30-1 U30-2 U31-1 U31-2 U32-1 U32-2 U33 U34 U35 U36 U37 X1 X2-1 X2-2 X3 X4 X5 X6 X6' X7 X8 X9 X10 X11 X12 X13 X13' X14 X15 X16 X17 X18 Z1-1 Z1-2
